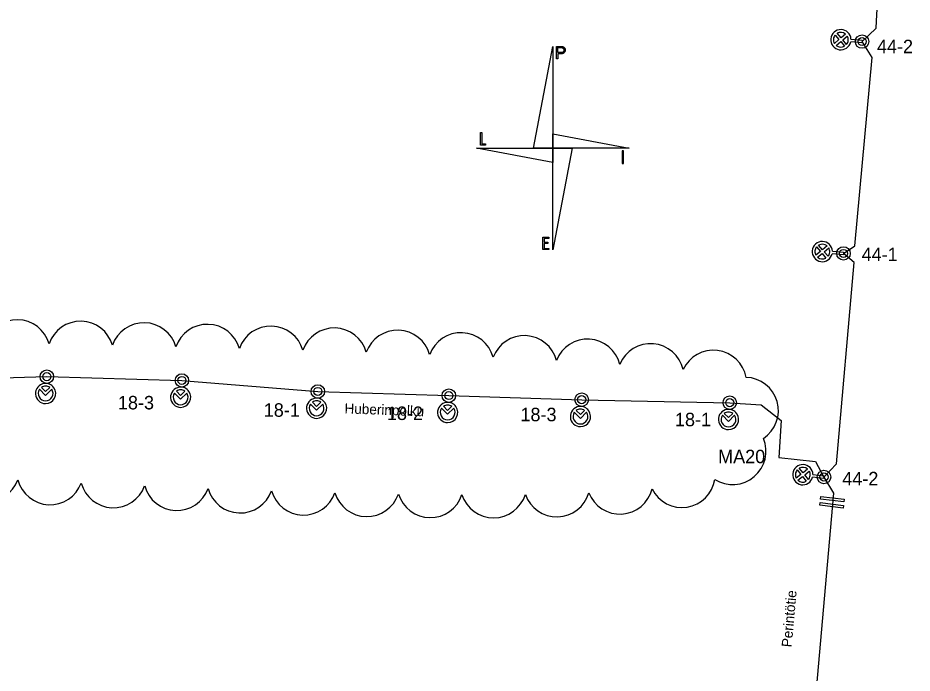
# Model space of a CAD drawing. Extents: x 25497851 to 25498523, y 6686544 to 6687372.
# Drawn here: x 25498079 to 25498277.9, y 6687110.6 to 6687256.4 of the extents above; entities that cross this region are included whole.
import ezdxf

# ---------------------------------------------------------------- set-up
doc = ezdxf.new("R2010")
doc.units = 0
for name, color, linetype in [('EL_CABLE_MAA', 7, 'Continuous'), ('KAAPELI', 7, 'Continuous'), ('KEYGWT_ANNOTATION', 7, 'Continuous'), ('MUU_SUUNNITELMAVIIVA', 7, 'Continuous'), ('MUU_UV-SUUNNITELMASYMBOLI', 7, 'Continuous'), ('PYLVAS', 7, 'Continuous'), ('TEKSTI_SUUNNITELMA-ALUE', 7, 'Continuous'), ('VALAISIN', 7, 'Continuous')]:
    doc.layers.add(name, color=color, linetype=linetype)

msp = doc.modelspace()

# ---------------------------------------------------------------- linework, layer by layer
at = {"layer": 'EL_CABLE_MAA'}
for points in [[(25498270.78, 6687293.04), (25498273.51, 6687291.57), (25498271.36, 6687281.07), (25498269.91, 6687255.77), (25498269.86, 6687254.08), (25498266.81, 6687251.14)], [(25498052.78, 6687175.51), (25498065.4, 6687175.42), (25498070.51, 6687176.14), (25498085.44, 6687176.58)], [(25498085.44, 6687176.58), (25498115.48, 6687175.73)], [(25498115.48, 6687175.73), (25498145.73, 6687173.28)], [(25498145.73, 6687173.28), (25498174.88, 6687172.36)], [(25498174.88, 6687172.36), (25498204.43, 6687171.45)], [(25498204.43, 6687171.45), (25498237.37, 6687170.78)]]:
    msp.add_lwpolyline(points, dxfattribs=at)
at = {"layer": 'KAAPELI'}
for points in [[(25498262.68, 6687204), (25498265.21, 6687205.67), (25498269.02, 6687247.64), (25498266.81, 6687251.15)], [(25498258.33, 6687154.24), (25498261.13, 6687157.19), (25498265.03, 6687202.01), (25498262.68, 6687204)], [(25498237.37, 6687170.78), (25498244.36, 6687170.34), (25498248.8, 6687166.85), (25498248.29, 6687158.61), (25498256.44, 6687157.66), (25498258.33, 6687154.24)], [(25498258.33, 6687154.24), (25498260.46, 6687150.68), (25498256.59, 6687106.94), (25498254.07, 6687104.33)]]:
    msp.add_lwpolyline(points, dxfattribs=at)
at = {"layer": 'MUU_SUUNNITELMAVIIVA'}
for centre, start, end in [((25498078.81, 6687181.85), 16.1083, 161.1083), ((25498092.93, 6687181.51), 16.1082, 161.1082), ((25498107.04, 6687181.17), 16.108, 161.108), ((25498121.16, 6687180.82), 16.0365, 161.0365), ((25498135.27, 6687180.43), 15.8641, 160.8641), ((25498149.37, 6687180.01), 15.656, 160.656), ((25498163.47, 6687179.52), 15.3981, 160.3981), ((25498177.57, 6687178.96), 15.0668, 160.0668), ((25498191.66, 6687178.31), 14.6186, 159.6186), ((25498205.73, 6687177.52), 13.9631, 158.9631), ((25498219.77, 6687176.52), 12.8637, 157.8637), ((25498233.72, 6687175.07), 10.3314, 155.3314), ((25498240.79, 6687169.01), 303.3285, 88.3285), ((25498238.02, 6687159.97), 237.71, 22.71), ((25498072.05, 6687156.17), 194.5929, 339.5929), ((25498086.15, 6687155.47), 194.7067, 339.7067), ((25498100.25, 6687154.8), 194.8683, 339.8683), ((25498226.75, 6687154.85), 206.1225, 351.1225), ((25498114.35, 6687154.19), 195.1319, 340.1319), ((25498128.45, 6687153.64), 195.4443, 340.4443), ((25498142.55, 6687153.18), 195.8224, 340.8224), ((25498156.64, 6687152.83), 196.2926, 341.2926), ((25498170.74, 6687152.61), 196.9001, 341.9001), ((25498198.9, 6687152.77), 198.952, 343.952), ((25498212.92, 6687153.38), 201.0464, 346.0464), ((25498184.83, 6687152.56), 197.7277, 342.7277)]:
    msp.add_arc(centre, 7.4, start, end, dxfattribs=at)
at = {"layer": 'MUU_UV-SUUNNITELMASYMBOLI'}
for p, q in [((25498181.91, 6687230.89), (25498182.18, 6687230.89)), ((25498181.91, 6687228.11), (25498181.91, 6687230.89)), ((25498182.18, 6687230.89), (25498182.18, 6687228.39)), ((25498183.01, 6687228.11), (25498181.91, 6687228.11)), ((25498182.18, 6687228.39), (25498183.01, 6687228.39)), ((25498183.01, 6687228.39), (25498183.01, 6687228.11)), ((25498195.77, 6687207.63), (25498197.15, 6687207.63)), ((25498195.77, 6687204.85), (25498195.77, 6687207.63)), ((25498197.15, 6687207.35), (25498196.05, 6687207.35)), ((25498196.05, 6687207.35), (25498196.05, 6687206.51)), ((25498196.05, 6687206.51), (25498196.87, 6687206.51)), ((25498196.87, 6687206.23), (25498196.05, 6687206.23)), ((25498196.05, 6687206.23), (25498196.05, 6687205.13)), ((25498196.87, 6687206.51), (25498196.87, 6687206.23)), ((25498197.15, 6687207.63), (25498197.15, 6687207.35)), ((25498197.15, 6687204.85), (25498195.77, 6687204.85)), ((25498196.05, 6687205.13), (25498197.15, 6687205.13)), ((25498197.15, 6687205.13), (25498197.15, 6687204.85)), ((25498257.41, 6687147.95), (25498257.48, 6687148.55)), ((25498257.48, 6687148.55), (25498262.69, 6687147.93)), ((25498257.57, 6687149.3), (25498257.64, 6687149.9)), ((25498262.78, 6687148.68), (25498257.57, 6687149.3)), ((25498257.64, 6687149.9), (25498262.85, 6687149.28)), ((25498262.85, 6687149.28), (25498262.78, 6687148.68)), ((25498262.62, 6687147.33), (25498257.41, 6687147.95)), ((25498262.69, 6687147.93), (25498262.62, 6687147.33))]:
    msp.add_line(p, q, dxfattribs=at)
for points in [[(25498193.68, 6687227.42), (25498197.99, 6687250.07), (25498197.99, 6687227.42)], [(25498197.99, 6687230.65), (25498214.97, 6687227.42), (25498197.99, 6687227.42)], [(25498197.99, 6687224.2), (25498181, 6687227.42), (25498197.99, 6687227.42)], [(25498202.29, 6687227.42), (25498197.99, 6687204.78), (25498197.99, 6687227.42)]]:
    msp.add_lwpolyline(points, close=True, dxfattribs=at)
for points in [[(25498198.83, 6687247.31), (25498198.83, 6687250.08), (25498199.94, 6687250.08)], [(25498199.94, 6687250.08), (25498200.02, 6687250.08), (25498200.11, 6687250.06), (25498200.19, 6687250.04), (25498200.27, 6687250.01), (25498200.35, 6687249.97), (25498200.42, 6687249.92), (25498200.49, 6687249.87), (25498200.55, 6687249.81), (25498200.61, 6687249.74), (25498200.65, 6687249.67), (25498200.69, 6687249.59), (25498200.72, 6687249.51), (25498200.75, 6687249.43), (25498200.76, 6687249.34), (25498200.76, 6687249.26), (25498200.76, 6687249.17), (25498200.75, 6687249.08), (25498200.72, 6687249), (25498200.69, 6687248.92), (25498200.65, 6687248.84), (25498200.61, 6687248.77), (25498200.55, 6687248.7), (25498200.49, 6687248.64), (25498200.42, 6687248.59), (25498200.35, 6687248.54), (25498200.27, 6687248.5), (25498200.19, 6687248.47), (25498200.11, 6687248.45), (25498200.02, 6687248.43), (25498199.94, 6687248.43)], [(25498199.94, 6687248.43), (25498199.11, 6687248.43), (25498199.11, 6687247.31), (25498198.83, 6687247.31)], [(25498199.11, 6687248.7), (25498199.11, 6687249.81), (25498199.94, 6687249.81)], [(25498199.94, 6687248.7), (25498199.11, 6687248.7)], [(25498199.94, 6687249.81), (25498199.99, 6687249.8), (25498200.05, 6687249.79), (25498200.11, 6687249.78), (25498200.16, 6687249.76), (25498200.21, 6687249.73), (25498200.26, 6687249.7), (25498200.31, 6687249.67), (25498200.35, 6687249.62), (25498200.38, 6687249.58), (25498200.41, 6687249.53), (25498200.44, 6687249.48), (25498200.46, 6687249.43), (25498200.48, 6687249.37), (25498200.48, 6687249.31), (25498200.49, 6687249.26), (25498200.48, 6687249.2), (25498200.48, 6687249.14), (25498200.46, 6687249.09), (25498200.44, 6687249.03), (25498200.41, 6687248.98), (25498200.38, 6687248.93), (25498200.35, 6687248.89), (25498200.31, 6687248.85), (25498200.26, 6687248.81), (25498200.21, 6687248.78), (25498200.16, 6687248.75), (25498200.11, 6687248.73), (25498200.05, 6687248.72), (25498199.99, 6687248.71), (25498199.94, 6687248.7)], [(25498213.47, 6687224.03), (25498213.75, 6687224.03), (25498213.75, 6687226.83), (25498213.47, 6687226.83), (25498213.47, 6687224.03)]]:
    msp.add_lwpolyline(points, dxfattribs=at)
at = {"layer": 'PYLVAS'}
for centre, radius in [((25498266.81, 6687251.15), 1.5), ((25498266.81, 6687251.15), 0.9), ((25498262.68, 6687204), 1.5), ((25498262.68, 6687204), 0.9), ((25498085.44, 6687176.58), 1.5), ((25498085.44, 6687176.58), 0.9), ((25498115.48, 6687175.73), 1.5), ((25498115.48, 6687175.73), 0.9), ((25498145.73, 6687173.28), 1.5), ((25498145.73, 6687173.28), 0.9), ((25498174.88, 6687172.36), 1.5), ((25498174.88, 6687172.36), 0.9), ((25498204.43, 6687171.45), 1.5), ((25498204.43, 6687171.45), 0.9), ((25498237.37, 6687170.78), 1.5), ((25498237.37, 6687170.78), 0.9), ((25498258.33, 6687154.24), 1.5), ((25498258.33, 6687154.24), 0.9)]:
    msp.add_circle(centre, radius, dxfattribs=at)
at = {"layer": 'VALAISIN'}
for p, q in [((25498260.81, 6687252.61), (25498261.66, 6687251.6)), ((25498262.12, 6687251.98), (25498261.27, 6687252.99)), ((25498263.14, 6687252.83), (25498262.12, 6687251.98)), ((25498262.51, 6687251.52), (25498263.52, 6687252.37)), ((25498261.66, 6687251.6), (25498260.65, 6687250.75)), ((25498261.04, 6687250.29), (25498262.05, 6687251.14)), ((25498262.05, 6687251.14), (25498262.9, 6687250.12)), ((25498263.36, 6687250.51), (25498262.51, 6687251.52)), ((25498266.78, 6687250.84), (25498264.28, 6687251.06)), ((25498264.33, 6687251.66), (25498266.83, 6687251.44)), ((25498266.83, 6687251.44), (25498266.78, 6687250.84)), ((25498257.53, 6687204.45), (25498256.52, 6687203.6)), ((25498256.68, 6687205.46), (25498257.53, 6687204.45)), ((25498257.99, 6687204.83), (25498257.14, 6687205.85)), ((25498259.01, 6687205.68), (25498257.99, 6687204.83)), ((25498258.38, 6687204.37), (25498259.39, 6687205.22)), ((25498259.23, 6687203.36), (25498258.38, 6687204.37)), ((25498260.2, 6687204.51), (25498262.7, 6687204.29)), ((25498262.7, 6687204.29), (25498262.65, 6687203.7)), ((25498256.9, 6687203.14), (25498257.92, 6687203.99)), ((25498257.92, 6687203.99), (25498258.77, 6687202.97)), ((25498262.65, 6687203.7), (25498260.15, 6687203.92)), ((25498083.8, 6687173.77), (25498085.16, 6687172.41)), ((25498085.16, 6687173.26), (25498084.23, 6687174.19)), ((25498086.1, 6687174.19), (25498085.16, 6687173.26)), ((25498085.16, 6687172.41), (25498086.52, 6687173.77)), ((25498113.84, 6687172.92), (25498115.2, 6687171.57)), ((25498115.2, 6687172.41), (25498114.27, 6687173.35)), ((25498116.14, 6687173.35), (25498115.2, 6687172.41)), ((25498115.2, 6687171.57), (25498116.56, 6687172.92)), ((25498144.09, 6687170.47), (25498145.45, 6687169.11)), ((25498145.45, 6687169.96), (25498144.52, 6687170.9)), ((25498146.39, 6687170.9), (25498145.45, 6687169.96)), ((25498145.45, 6687169.11), (25498146.81, 6687170.47)), ((25498173.25, 6687169.55), (25498174.61, 6687168.19)), ((25498174.61, 6687169.03), (25498173.67, 6687169.97)), ((25498175.54, 6687169.97), (25498174.61, 6687169.03)), ((25498174.61, 6687168.19), (25498175.97, 6687169.55)), ((25498202.79, 6687168.64), (25498204.15, 6687167.28)), ((25498204.15, 6687168.13), (25498203.22, 6687169.06)), ((25498205.09, 6687169.06), (25498204.15, 6687168.13)), ((25498204.15, 6687167.28), (25498205.51, 6687168.64)), ((25498237.09, 6687167.46), (25498236.16, 6687168.4)), ((25498238.03, 6687168.4), (25498237.09, 6687167.46)), ((25498235.73, 6687167.97), (25498237.09, 6687166.61)), ((25498237.09, 6687166.61), (25498238.45, 6687167.97)), ((25498253.2, 6687154.8), (25498252.17, 6687153.98)), ((25498252.37, 6687155.83), (25498253.2, 6687154.8)), ((25498253.67, 6687155.18), (25498252.84, 6687156.21)), ((25498254.7, 6687156), (25498253.67, 6687155.18)), ((25498254.04, 6687154.71), (25498255.07, 6687155.53)), ((25498254.87, 6687153.67), (25498254.04, 6687154.71)), ((25498255.87, 6687154.8), (25498258.36, 6687154.53)), ((25498258.36, 6687154.53), (25498258.3, 6687153.93)), ((25498252.54, 6687153.51), (25498253.57, 6687154.33)), ((25498253.57, 6687154.33), (25498254.4, 6687153.3)), ((25498258.3, 6687153.93), (25498255.8, 6687154.21))]:
    msp.add_line(p, q, dxfattribs=at)
for centre, radius, start, end in [((25498262.09, 6687251.56), 2.25, 2.6413, 174.979), ((25498262.09, 6687251.56), 1.65, 140.4547, 174.979), ((25498262.09, 6687251.56), 1.65, 50.4547, 119.5033), ((25498262.09, 6687251.56), 1.65, 354.979, 29.5033), ((25498262.09, 6687251.56), 2.25, 174.979, 347.3167), ((25498262.09, 6687251.56), 1.65, 174.979, 209.5033), ((25498262.09, 6687251.56), 1.65, 230.4547, 299.5033), ((25498262.09, 6687251.56), 1.65, 320.4547, 354.979), ((25498257.96, 6687204.41), 2.25, 2.6413, 174.979), ((25498257.96, 6687204.41), 2.25, 174.979, 347.3167), ((25498257.96, 6687204.41), 1.65, 140.4547, 174.979), ((25498257.96, 6687204.41), 1.65, 174.979, 209.5033), ((25498257.96, 6687204.41), 1.65, 50.4547, 119.5033), ((25498257.96, 6687204.41), 1.65, 320.4547, 354.979), ((25498257.96, 6687204.41), 1.65, 354.979, 29.5033), ((25498257.96, 6687204.41), 1.65, 230.4547, 299.5033), ((25498085.16, 6687172.83), 2.25, 97.6623, 270), ((25498085.16, 6687172.83), 1.65, 90, 124.5243), ((25498085.16, 6687172.83), 2.25, 270, 97.6623), ((25498085.16, 6687172.83), 1.65, 55.4757, 90), ((25498085.16, 6687172.83), 1.65, 145.4757, 270), ((25498085.16, 6687172.83), 1.65, 270, 34.5243), ((25498115.2, 6687171.99), 2.25, 97.6623, 270), ((25498115.2, 6687171.99), 1.65, 145.4757, 270), ((25498115.2, 6687171.99), 1.65, 90, 124.5243), ((25498115.2, 6687171.99), 2.25, 270, 97.6623), ((25498115.2, 6687171.99), 1.65, 55.4757, 90), ((25498115.2, 6687171.99), 1.65, 270, 34.5243), ((25498145.45, 6687169.54), 2.25, 97.6623, 270), ((25498145.45, 6687169.54), 1.65, 145.4757, 270), ((25498145.45, 6687169.54), 1.65, 90, 124.5243), ((25498145.45, 6687169.54), 2.25, 270, 97.6623), ((25498145.45, 6687169.54), 1.65, 55.4757, 90), ((25498145.45, 6687169.54), 1.65, 270, 34.5243), ((25498174.61, 6687168.61), 2.25, 97.6623, 270), ((25498174.61, 6687168.61), 2.25, 270, 97.6623), ((25498174.61, 6687168.61), 1.65, 145.4757, 270), ((25498174.61, 6687168.61), 1.65, 90, 124.5243), ((25498174.61, 6687168.61), 1.65, 55.4757, 90), ((25498174.61, 6687168.61), 1.65, 270, 34.5243), ((25498204.15, 6687167.7), 2.25, 97.6623, 270), ((25498204.15, 6687167.7), 1.65, 145.4757, 270), ((25498204.15, 6687167.7), 1.65, 90, 124.5243), ((25498204.15, 6687167.7), 2.25, 270, 97.6623), ((25498204.15, 6687167.7), 1.65, 55.4757, 90), ((25498204.15, 6687167.7), 1.65, 270, 34.5243), ((25498237.09, 6687167.04), 2.25, 97.6623, 270), ((25498237.09, 6687167.04), 1.65, 90, 124.5243), ((25498237.09, 6687167.04), 2.25, 270, 97.6623), ((25498237.09, 6687167.04), 1.65, 55.4757, 90), ((25498237.09, 6687167.04), 1.65, 145.4757, 270), ((25498237.09, 6687167.04), 1.65, 270, 34.5243), ((25498253.62, 6687154.75), 2.25, 1.2856, 173.6233), ((25498253.62, 6687154.75), 1.65, 49.099, 118.1477), ((25498253.62, 6687154.75), 2.25, 173.6233, 345.9611), ((25498253.62, 6687154.75), 1.65, 173.6233, 208.1477), ((25498253.62, 6687154.75), 1.65, 139.099, 173.6233), ((25498253.62, 6687154.75), 1.65, 319.099, 353.6233), ((25498253.62, 6687154.75), 1.65, 353.6233, 28.1477), ((25498253.62, 6687154.75), 1.65, 229.099, 298.1477)]:
    msp.add_arc(centre, radius, start, end, dxfattribs=at)

# ---------------------------------------------------------------- texts
at = {"layer": 'KEYGWT_ANNOTATION'}
for s, p in [('44-2', (25498270.11, 6687248.56)), ('44-1', (25498266.7, 6687202.28)), ('18-3', (25498101.25, 6687169.29)), ('18-1', (25498133.69, 6687167.65)), ('18-2', (25498161.1, 6687166.93)), ('18-3', (25498190.8, 6687166.65)), ('18-1', (25498225.18, 6687165.54)), ('MA20', (25498234.78, 6687157.31)), ('44-2', (25498262.41, 6687152.39))]:
    msp.add_text(s, height=3, dxfattribs=at).set_placement(p)
at = {"layer": 'TEKSTI_SUUNNITELMA-ALUE'}
for s, rotation, p in [('Huberinpolku', 357.849, (25498151.63, 6687168.41)), ('Perintötie', 84.8782, (25498251.13, 6687116.28))]:
    msp.add_text(s, height=2.25, rotation=rotation, dxfattribs=at).set_placement(p)

doc.saveas('drawing.dxf')
